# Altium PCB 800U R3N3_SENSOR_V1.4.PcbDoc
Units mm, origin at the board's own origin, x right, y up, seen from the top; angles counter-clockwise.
Board outline 152.4 x 101.6 mm, 2 copper layers (Top Layer, Bottom Layer); 17 components, 10 nets, 29 pads, 17 vias.
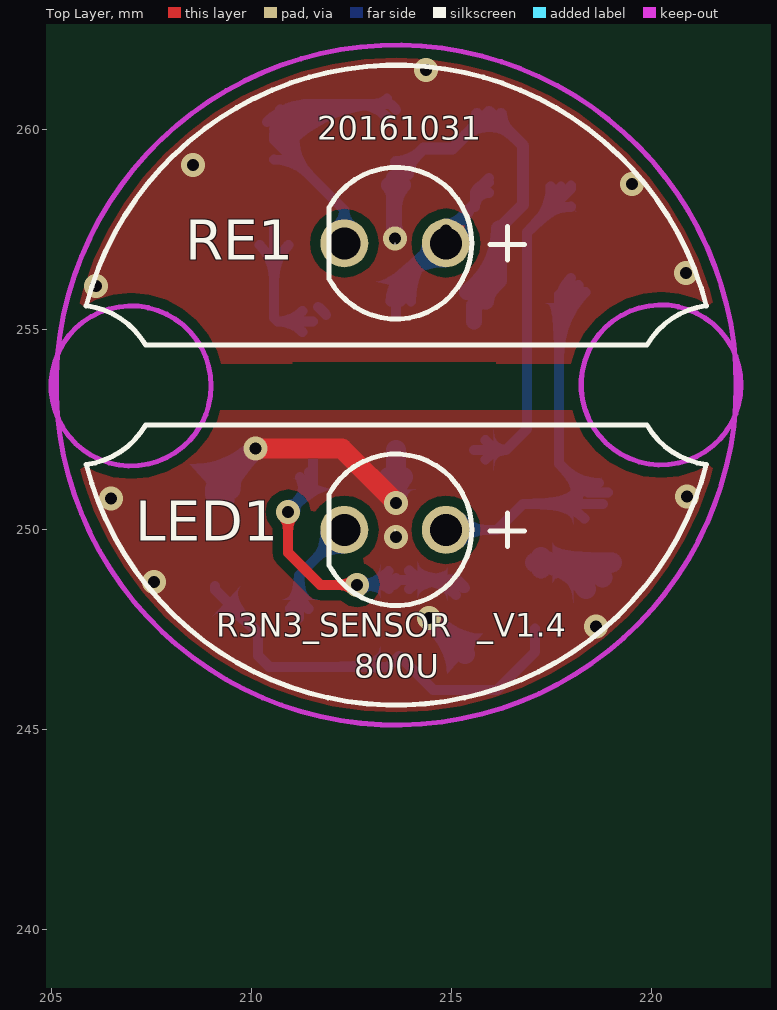
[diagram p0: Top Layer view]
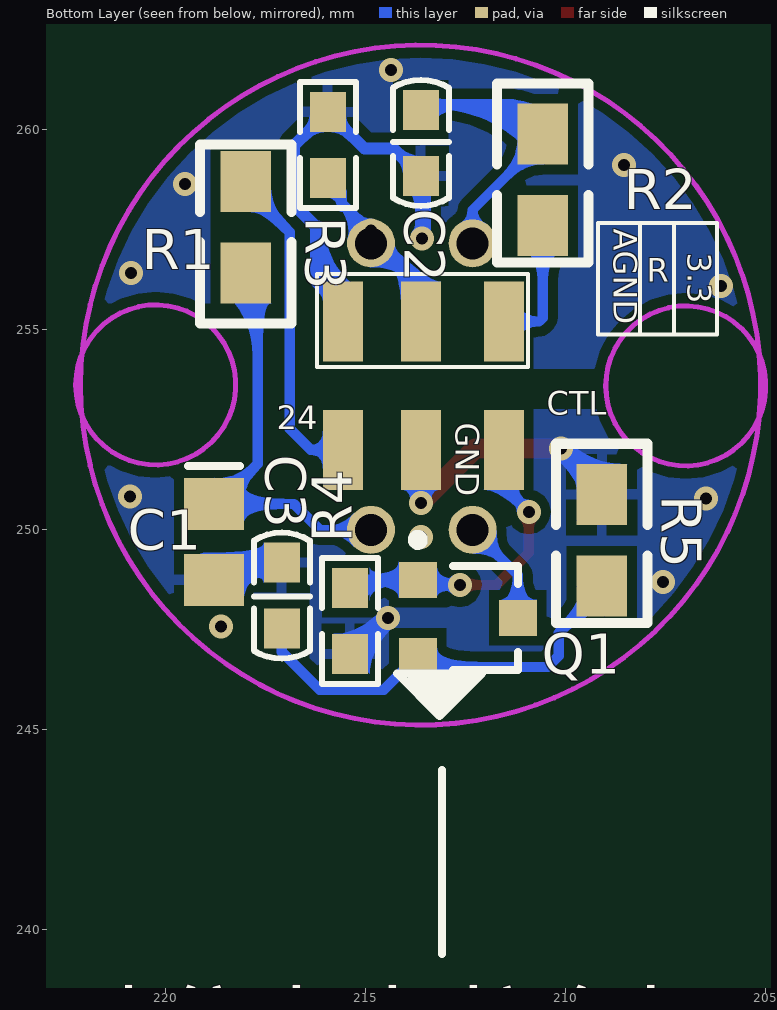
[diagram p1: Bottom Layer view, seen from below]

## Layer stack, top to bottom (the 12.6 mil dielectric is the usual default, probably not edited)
Top Layer: signal copper 0.0356
Dielectric: dielectric 0.32, FR-4, Dk 4.8
Bottom Layer: signal copper 0.0356

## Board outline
162.425,214.025 314.825,214.025 314.825,315.625 162.425,315.625

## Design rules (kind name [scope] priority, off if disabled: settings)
Clearance [All] p1: gap=0.25
FabricationTestpoint [(IsPad And (OnTopLayer Or OnBottomLayer))] p1: side=3 testpointundercomponent=TRUE minsize=1.016 maxsize=2.54 preferedsize=1.524 minholesize=0 maxholesize=1.016 preferedholesize=0.813 testpointgrid=0.025 allowsidetop=TRUE allowsidebottom=TRUE usegrid=TRUE gridtolerance=0
PlaneConnect [Isvia] p1: planeconnectstyle=Relief reliefexpansion=0.508 reliefentries=4 reliefconductorwidth=0.254 reliefairgap=0.254
PolygonConnect [Isvia] p1: connectstyle=Direct reliefconductorwidth=0.254 reliefentries=4 polygonreliefangle="90 Angle" airgapwidth=0.254
RoutingVias [All] p1: holewidth=0.3 width=0.6 viastyle="Through Hole" minholewidth=0.3 minwidth=0.6 maxholewidth=0.3 maxwidth=0.6
SilkToSolderMaskClearance SilkscreenOverComponentPads [IsPad] p1: minsilkscreentomaskgap=0.254 clearancetoexposedcopper=TRUE
SolderMaskExpansion [All] p1: expansion=0.102
Width [All] p1: maxlimit=0.6 minlimit=0.254 preferedwidth=0.254 minimp=50.000000 maximp=50.000000 favimp=50.000000
25 further rules are at their usual default settings.

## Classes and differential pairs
component class "800U R3N3_TR": 3.3 24 C1 C2 C3 CTL GND LED1 Q1 R R1 R2 R3 R4 R5 RE1

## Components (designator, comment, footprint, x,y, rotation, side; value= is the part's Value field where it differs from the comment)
3.3 "" HOLE_SMD 211.55,255.21 r180 bottom (schematic designator 2)
24 "" HOLE_SMD 215.575,252 r180 bottom (schematic designator 1)
AGND "" HOLE_SMD 215.575,255.21 r180 bottom (schematic designator LEDCTL1)
C1 "105" C0805 218.8,249.7 r270 bottom
C2 "105" C0603 213.625,260.5 r270 bottom
C3 "102" C0603 217.1,247.53 r90 bottom
CTL "" HOLE_SMD 211.55,252 r180 bottom (schematic designator LEDCTL1)
GND "" HOLE_SMD 213.625,252 r180 bottom (schematic designator GND1)
LED1 "SIR67-21C" LED-2.54-3 213.6,250 r180 top
Q1 "MMBT5551" SOT-23 212.45,247.8 r270 bottom
R "" HOLE_SMD 213.625,255.21 r180 bottom (schematic designator LED_R1)
R1 "100" R0805 218,257.57 r90 bottom
R2 "100" R0805 210.575,258.75 r270 bottom
R3 "10K" R0603 215.95,260.45 r270 bottom
R4 "10K" R0603 215.4,246.9 r90 bottom
R5 "15" R0805 209.1,249.74 r270 bottom
RE1 "PD70-01C" LED-2.54-3 213.6,257.165 r180 top

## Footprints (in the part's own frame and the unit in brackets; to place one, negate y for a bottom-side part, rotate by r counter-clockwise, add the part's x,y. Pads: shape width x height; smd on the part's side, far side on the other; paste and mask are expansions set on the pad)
C0603 [mm]
  rect 1x0.9 smd: 1(0,0) 2(1.65,0)
  silkscreen extent -0.75,-0.7 2.4,0.7
C0805 [mm] "Chip Capacitor; Body 2.0 x"
  rect 1.3x1.5 smd: 1(-0.95,0) 2(0.95,0)
  silkscreen extent -1.9,-0.65 -1.9,0.65
HOLE_SMD [mm]
  rect 1x2 smd: 1(0,0)
LED-2.54-3 [mm]
  round 1.2 hole 0.8: 1(-1.27,0) 2(1.27,0)
  silkscreen extent -3.23,-1.89 1.65,1.89
R0603 [mm]
  rect 1x0.9 smd: 1(0,0) 2(1.65,0)
  silkscreen extent -0.75,-0.7 2.4,0.7
R0805 [mil]
  rect 60x50 smd: 1(-45,0) 2(45,0)
  silkscreen extent -95,-45 81,45
SOT-23 [mm] "SOT-23; 3 Leads; Body 3.0 x 2.6 mm"
  rect 0.9x0.95 smd: 1(-0.95,-1.25) 2(0.95,-1.25) 3(0,1.25)
  silkscreen extent -2.07,-1.38 1.3,1.25

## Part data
3.3 24 AGND CTL GND R: library part 焊
C1: library part Cap, "贴片电容"
C2 C3: library part Cap, "贴"
LED1: library part LED0, "贴"
Q1: library part NPN, "贴片NPN三极管"
R1 R2 R3 R4 R5: library part "Res Semi", "贴"
RE1: library part "Photo Sen", "贴"

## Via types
v1: diameter 0.6, hole 0.3, Top Layer to Bottom Layer, 17 vias

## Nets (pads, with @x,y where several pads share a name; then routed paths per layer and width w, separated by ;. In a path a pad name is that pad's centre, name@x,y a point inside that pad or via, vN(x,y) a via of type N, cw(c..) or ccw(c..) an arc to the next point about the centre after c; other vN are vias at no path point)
3.3V: 3.3.1 R2.2 | length 6.9
  Bottom Layer w0.254: R2.2@210.216,257.12 cw(c209.349,256.253) 210.575,256.253 cw(c211.801,256.253) R2.2@210.934,257.12 ; R2.2 210.575,255.3 210.665,255.21 ; 3.3.1@211.283,254.95 ccw(c210.665,254.347) 210.665,255.21 ; 3.3.1@211.283,255.47 cw(c210.665,256.073) 210.665,255.21 ; 3.3.1 210.665,255.21 ; 3.3.1@211.675,255.575 3.3.1@211.875,255.375
+24V: 24.1 R1.2 | length 11.8
  Bottom Layer w0.254: 24.1 216.375,252 ; 24.1@215.861,251.76 cw(c216.375,251.329) 216.375,252 ; 24.1@215.861,252.24 ccw(c216.375,252.671) 216.375,252 ; 217.1,257.64 ccw(c216.155,258.586) R1.2@217.492,258.586 ; 217.211,257.751 cw(c218,256.963) R1.2@218,258.078 ; R1.2@217.534,258.074 ccw(c217.022,258.586) R1.2@217.746,258.586 ; R1.2@218,258.613 218,258.54 216.9,257.44 216.9,252.525 216.375,252
AGND: AGND.1 C2.2 R3.1 | length 21.4
  Bottom Layer w0.3: C2.2 214.312,259.537 215.037,259.537 R3.1 216.8,259.6 216.8,258.134 216.2,257.534 ; C2.2@213.625,259.2 ccw(c213.625,260.045) 214.222,259.447 ; C2.2@213.925,258.9 cw(c214.529,258.9) 214.102,259.327 ; 215.353,259.853 cw(c215.95,259.255) 215.95,260.1 cw(c215.95,259.255) 216.547,259.853 ; 215.473,259.973 ccw(c215.046,260.4) R3.1@215.65,260.4 ; R3.1@216.25,260.4 ccw(c216.854,260.4) 216.427,259.973
  Bottom Layer w0.4: 213.575,257.592 ccw(c213.902,257.592) v1@213.671,257.361 ; 213.575,258.148 cw(c214.183,258.148) C2.2@213.788,258.61 ; 213.575,258.15 213.575,257.975 ; C2.2@213.575,258.8 213.575,257.975 ; v1(213.6,257.29) 213.575,257.315 213.575,257.975 ; AGND.1@215.398,255.952 ccw(c214.239,257.534) 216.2,257.534 216.2,256.235 ; AGND.1 215.575,255.61 216.2,256.235 ; AGND.1@215.596,256.009 ccw(c215.65,256.784) 216.2,256.235 ; AGND.1@215.634,255.629 ccw(c214.817,256.745) 216.2,256.745 ; AGND.1@215.875,255.71 cw(c216.358,255.71) AGND.1@216.016,256.051 ; C2.2@213.448,258.623 cw(c213.142,258.317) 213.575,258.317 ; C2.2@213.448,258.623 cw(c213.142,258.317) 213.575,258.317 ; C2.2@213.448,258.623 cw(c213.142,258.317) 213.575,258.317 ; 213.575,258.076 cw(c214.349,258.076) 213.802,258.623 ccw(c214.349,258.076) 213.575,258.076
  other v1: 206.125,256.1 220.875,256.42 219.525,258.65 208.55,259.125 214.375,261.5
GND: C1.2 C3.2 GND.1 R4.1 R5.1 | length 16.2
  Top Layer w0.5: v1@210.105,252.03 212.27,252.03 v1(213.625,250.675)
  Bottom Layer w0.5: R5.1 209.1,251.025 v1(210.115,252.04) ; R5.1@209.1,251.395 ccw(c209.1,252.288) 209.732,251.657 ; R5.1@209.485,251.01 cw(c210.451,251.01) 209.768,251.693 ; GND.1@213.448,251.323 cw(c213.021,250.896) 213.625,250.896 cw(c214.229,250.896) GND.1@213.802,251.323 ; v1(213.625,250.675) GND.1 ; v1(214.45,247.8) R4.1@215.35,246.9 ; 214.923,247.327 ccw(c215.35,247.754) R4.1@215.35,247.15 ; C3.2@217.241,249.039 cw(c217.583,248.697) 217.583,249.18 cw(c217.583,249.663) C3.2@217.241,249.321 ; C1.2@218.064,249.18 cw(c218.064,248.302) C1.2@218.782,248.808 ; C1.2@218.373,248.52 ccw(c217.1,247.623) C3.2 C1.2@219.025,249.18
  other v1: 218.625,247.59 207.575,248.7 213.625,249.825 206.5,250.78 220.9,250.84
LEDCTL: CTL.1 Q1.1 R4.2 | length 16
  Top Layer w0.254: v1@210.803,250.328 cw(c210.507,250.032) 210.925,250.032 cw(c211.343,250.032) v1@211.047,250.328 ; v1(210.925,250.45) 210.925,249.425 211.725,248.625 v1(212.65,248.625) ; v1@212.528,248.503 ccw(c212.232,248.207) 212.232,248.625 ccw(c212.232,249.043) v1@212.528,248.747
  Bottom Layer w0.254: v1(210.925,250.45) 211.55,251.075 CTL.1 ; v1@210.925,250.623 ccw(c210.925,251.041) 211.22,250.745 ccw(c211.516,250.45) v1@211.098,250.45 ; 211.138,250.663 ccw(c210.753,251.047) CTL.1@211.226,251.316 ; 211.373,250.898 ccw(c211.054,251.218) CTL.1@211.447,251.441 ; v1@212.772,248.503 cw(c213.068,248.207) 213.068,248.625 cw(c213.068,249.043) v1@212.772,248.747 ; 213.197,248.625 cw(c213.197,248.272) Q1.1@213.447,248.522 ; Q1.1@213.231,248.625 ccw(c213.231,249.161) Q1.1@213.624,248.797 ; Q1.1@213.438,248.969 cw(c212.65,249.698) v1(212.65,248.625) 213.575,248.625 Q1.1 215.15,248.75 R4.2@215.35,248.55 ; Q1.1@213.953,248.522 cw(c214.505,247.97) 214.505,248.75 cw(c214.505,249.53) Q1.1@213.953,248.978 ; 214.208,248.75 cw(c214.208,247.458) R4.2@215.122,248.372 ; 214.821,248.75 cw(c214.821,248.071) R4.2@215.301,248.551
NetC1_1: C1.1 LED1.1 R1.1 | length 18.4
  Bottom Layer w0.254: LED1.1 216.15,250 216.8,250.65 C1.1 ; 217.7,254.349 cw(c219.951,254.349) R1.1@218.359,255.941 ; 217.7,254.963 cw(c219.337,254.963) R1.1@218.18,256.12 ; 217.7,255.576 cw(c218.724,255.576) R1.1@218,256.3 ; C1.1@218.177,250.65 ccw(c216.914,250.65) 217.807,251.543 ccw(c218.7,252.436) C1.1@218.7,251.173 ; R1.1@218.225,256.007 217.827,256.007 217.7,255.88 217.7,251.65 218.42,250.93 C1.1@218.925,250.93 ; C1.1@218.33,250.28 ccw(c217.437,249.387) 217.437,250.65 ccw(c217.437,251.913) C1.1@218.33,251.02
NetC2_1: C2.1 R2.1 RE1.2 | length 20.6
  Bottom Layer w0.254: R2.1@210.395,260.199 cw(c211.484,259.111) 211.484,260.65 ; R2.1@210.575,259.258 cw(c210.575,258.069) 211.416,258.909 ; R2.1@210.575,260.02 cw(c212.097,258.498) 212.097,260.65 ; R2.1@210.729,260.504 ccw(c210.911,261.072) 211.332,260.65 ; R2.1@210.755,259.84 cw(c212.71,257.884) 212.71,260.65 ; R2.1@210.829,259.766 ccw(c211.48,259.766) R2.1@211.02,259.305 ; R2.1@210.934,259.66 cw(c213.323,257.271) C2.1@213.323,260.65 ; R2.1@211.083,259.766 ccw(c212.347,259.766) 211.453,258.872 ; R2.1@211.083,260.03 cw(c211.935,260.047) 211.332,260.65 ; RE1.2@212.089,257.572 ccw(c211.838,257.995) 212.33,257.995 ; RE1.2 212.33,257.995 ; RE1.2@212.571,257.572 cw(c212.822,257.995) 212.33,257.995 ; 212.604,260.65 cw(c212.604,259.529) C2.1@213.397,260.322 ; 213.087,260.65 ccw(c213.087,261.088) C2.1@213.397,260.778 ; C2.1 213.475,260.65 211.332,260.65 ; 211.332,260.65 R2.1 210.575,259.75 212.33,257.995
NetC3_1: C3.1 Q1.2 R5.2 | length 10.7
  Bottom Layer w0.254: R5.2 209.1,248.5 210.175,247.425 210.175,246.85 210.45,246.575 213.425,246.575 Q1.2 214.55,246 216.15,246 217.1,246.95 C3.1
NetLED1_2: LED1.2 Q1.3 | length 3.9
  Bottom Layer w0.254: Q1.3@210.972,248.028 ccw(c210.42,248.58) 211.2,248.58 ccw(c211.98,248.58) Q1.3@211.428,248.028 ; Q1.3 211.2,248.87 LED1.2
NetLED_R1_1: R3.2 R.1 RE1.1 | length 15.1
  Bottom Layer w0.254: R.1@213.49,255.71 cw(c214.347,255.71) 213.741,256.316 ; R.1@213.585,256.16 cw(c214.87,254.874) RE1.1@214.87,256.692 ; R.1@213.625,255.375 213.625,256.2 215.595,258.17 ; R.1@213.744,255.71 cw(c215.214,255.71) 214.175,256.75 ; R.1@213.998,255.71 cw(c216.081,255.71) RE1.1@214.608,257.183 ; 214.018,256.593 cw(c214.87,255.741) RE1.1@214.87,256.946 ; 214.261,256.836 ccw(c213.931,257.165) RE1.1@214.397,257.165 ; RE1.1@214.558,257.133 ccw(c214.212,257.48) RE1.1@214.702,257.48 ; RE1.1@214.631,257.206 cw(c214.875,256.962) RE1.1@214.875,257.307 ; RE1.1@214.87,257.638 ccw(c214.87,258.104) 215.199,257.774 ; RE1.1@214.875,257.653 ccw(c214.875,258.143) 215.222,257.797 ; RE1.1@215.048,257.48 cw(c215.393,257.48) 215.149,257.724 ; RE1.1@215.084,257.212 cw(c215.75,257.36) 215.268,257.843 ; RE1.1@215.332,257.267 cw(c216.286,257.479) 215.595,258.17 ; 215.595,258.07 cw(c215.952,258.07) R3.2@215.951,258.427 ; R3.2@215.595,258.325 cw(c215.951,258.325) R3.2@215.95,258.681 ; R3.2 215.595,258.445 215.595,258.17
  other v1: 214.875,257.48

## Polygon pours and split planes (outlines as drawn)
AGND on Top Layer "Mechanical 1-No Net" (solid, remove dead copper, pour order 1000): 205,262.175 222.1,262.175 222.125,262.15 222.125,254.15 205.05,254.15 205.025,254.175
GND on Top Layer "T" (solid, remove dead copper, pour order 8): 205.175,252.99 222.175,252.99 222.175,245.14 205.345,245.14 205.225,245.26 205.195,245.23 205.175,245.23
AGND on Bottom Layer "Mechanical 1-No Net" (solid, remove dead copper, pour order 1001): 205.2,261.95 222.125,261.95 222.15,261.975 222.15,254.1 222.225,254.025 205.3,254.025 205.25,253.975
GND on Bottom Layer "B" (solid, remove dead copper, pour order 6): 205,253.02 222.525,253.02 222.525,245.045 222.5,245.02 205.065,245.02 205.025,244.98

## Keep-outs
Keep-Out Layer:
  circle w0.127: c213.629,253.619 r8.5
  circle w0.127: c220.25,253.625 r2
  circle w0.127: c207,253.6 r2

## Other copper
Top Layer:
  pour cut-out: 211.025,254.2 216.125,254.2 216.125,253 211.025,253
Bottom Layer:
  pour cut-out: 211.025,254.2 216.125,254.2 216.125,253 211.025,253
  pour cut-out: 214.3,256.24 216.31,256.24 216.34,256.21 216.34,254.18 214.285,254.18 214.275,254.17
  pour cut-out: 218.175,255.66 222.105,255.66 222.125,255.68 222.125,251.625 222.15,251.6 218.195,251.6 218.175,251.58
  pour cut-out: 212.675,253.26 214.4,253.26 214.925,253.26 214.85,250.94 214.4,250.94 212.671,250.94 212.611,251 212.275,251 212.275,252.125 212.275,253.26
  pour cut-out: 216.079,256.2 216.75,256.2 216.75,255.85 216.725,255.825 216.075,255.825 216.075,256.204
  pour cut-out: 218.268,257.872 218.885,257.872 218.885,257.25 218.325,257.25 218.325,257.815

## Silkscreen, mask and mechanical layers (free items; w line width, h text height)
Top Overlay:
  lines w0.127: 205.879,251.635 ccw(c205.629,253.619) 207.362,252.621 219.896,252.621 ccw(c221.629,253.619) 221.379,251.635 cw(c213.629,253.619) 205.879,251.635 ; 205.879,255.603 cw(c205.629,253.619) 207.362,254.617 219.896,254.617 cw(c221.629,253.619) 221.379,255.603 ccw(c213.629,253.619) 205.879,255.603
  text "20161031" at 211.65,259.55 h1
  text "R3N3_SENSOR" at 209.125,247.125 h1
  text "_V1.4" at 215.65,247.125 h1
  text "800U" at 212.575,246.1 h1
Bottom Overlay:
  lines w0.1: 207.3,254.955 207.3,257.675 ; 208.15,254.905 208.15,257.625 ; 206.225,254.88 206.225,257.67 209.2,257.67 209.2,254.88 206.225,254.88 ; 210.95,254.07 210.95,256.4 216.225,256.4 216.225,254.07 210.95,254.07
  lines w0.2: 212.775,246.37 213.447,245.697 ; 213.035,246.39 213.552,245.872 ; 213.1,239.4 213.1,244 ; 213.225,246.31 213.611,245.921 ; 213.254,245.45 212.294,246.41 214.214,246.41 213.154,245.35 212.094,246.41 212.494,246.41 213.342,245.562 ; 213.3,246.38 213.725,245.96 ; 213.57,246.345 213.832,246.082 ; 213.736,246.404 213.95,246.18
  text "对应外壳卡位标志" at 205.975,236.1 h3
Mechanical 1:
  circle w0.127: c207,253.6 r1.2
  circle w0.127: c220.25,253.625 r1.2
  circle w0.127: c213.629,253.619 r8.5
  lines w0.2: 210.775,253 216.35,253 216.35,254.2 210.775,254.2 210.775,253
Mechanical 3:
  lines w0.1: 205.1,253.6 222.129,253.6
  lines w0.127: 209.898,259.72 217.398,259.72 ; 209.987,259.723 ccw(c209.987,259.134) 209.398,259.134 209.398,254.72 ccw(c209.898,254.72) 209.898,254.22 217.398,254.22 ccw(c217.398,254.72) 217.898,254.72 217.898,259.22 ; 217.309,259.727 cw(c217.309,259.138) 217.898,259.138 ; 209.398,247.92 ccw(c209.898,247.92) 209.898,247.42 217.398,247.42 ccw(c217.398,247.92) 217.898,247.92 217.898,252.42 ccw(c217.398,252.42) 217.398,252.92 209.898,252.92 ccw(c209.898,252.42) 209.398,252.42 209.398,247.92
  lines w0.2: 213.625,245.45 213.625,261.5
